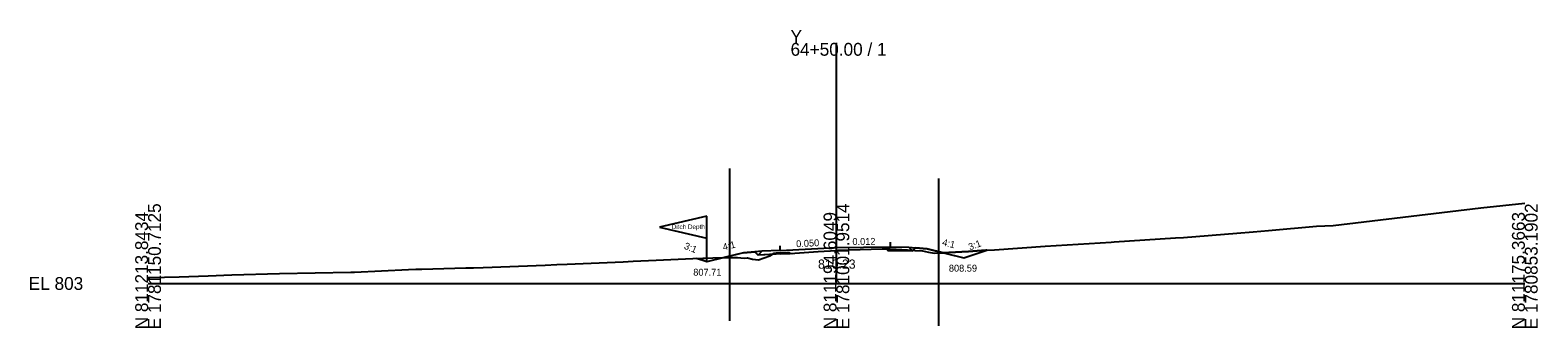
# Model space of a CAD drawing. Extents: x -12583 to 5303, y -44 to 25667.
# Drawn here: x 4974.3 to 5302.8, y 4990.3 to 5055.3 of the extents above; entities that cross this region are included whole.
import ezdxf

# ---------------------------------------------------------------- set-up
doc = ezdxf.new("R2010")
doc.units = 0
for name, color, linetype in [('Exist Cross Section Cell', 7, 'Continuous'), ('Exist XS Center Line Elevation Label', 7, 'Continuous'), ('Exist XS Ground Line', 7, 'Continuous'), ('Prop XS Ditch Slope Text', 7, 'Continuous'), ('Prop XS Ditch Standard Text', 7, 'Continuous'), ('Prop XS Dump Level', 7, 'Continuous'), ('Prop XS Earthwork Shape', 7, 'Continuous'), ('Prop XS EOT Tick Mark', 7, 'Continuous'), ('Prop XS Exc Vertical Line 1', 7, 'Continuous'), ('Prop XS Exc Vertical Line 2', 7, 'Continuous'), ('Prop XS Finish Grade', 7, 'Continuous'), ('Prop XS Finish Grade Earthwork', 7, 'Continuous'), ('Prop XS Finish Grade Paved Shoulder', 7, 'Continuous'), ('Prop XS Finish Grade Pavement', 7, 'Continuous'), ('Prop XS Pvmt Edge Slope', 7, 'Continuous'), ('Prop XS SE Text', 7, 'Continuous'), ('Prop XS Side Slope Text', 7, 'Continuous'), ('Prop XS Subgrade Earthwork', 7, 'Continuous'), ('Scratch_Level_3', 7, 'Continuous')]:
    doc.layers.add(name, color=color, linetype=linetype)

msp = doc.modelspace()

# ---------------------------------------------------------------- linework, layer by layer
at = {"layer": 'Exist Cross Section Cell'}
for p, q in [((5150, 5000), (5150, 5052.51)), ((5000, 5000), (5150, 5000)), ((5150, 5000), (5300, 5000))]:
    msp.add_line(p, q, dxfattribs=at)
at = {"layer": 'Exist XS Ground Line'}
for p, q in [((5290.45, 5016.51), (5300, 5017.5)), ((5258.26, 5012.65), (5290.45, 5016.51)), ((5225.66, 5010.04), (5237.25, 5010.99)), ((5237.25, 5010.99), (5240.79, 5011.24)), ((5240.79, 5011.24), (5244.18, 5011.56)), ((5244.18, 5011.56), (5254.6, 5012.48)), ((5254.6, 5012.48), (5258.26, 5012.65)), ((5139.9, 5006.57), (5146.05, 5007)), ((5146.05, 5007), (5150, 5007.23)), ((5150, 5007.23), (5150.4, 5007.25)), ((5150.4, 5007.25), (5159.95, 5007.53)), ((5159.95, 5007.53), (5161.22, 5007.57)), ((5161.22, 5007.57), (5161.69, 5007.54)), ((5161.69, 5007.54), (5163.01, 5007.47)), ((5163.01, 5007.47), (5167.07, 5007.23)), ((5167.07, 5007.23), (5168.78, 5007.13)), ((5168.78, 5007.13), (5170.03, 5006.85)), ((5170.03, 5006.85), (5171.35, 5006.6)), ((5174.5, 5006.79), (5178.76, 5007)), ((5178.76, 5007), (5182.57, 5007.24)), ((5182.57, 5007.24), (5184.42, 5007.37)), ((5184.42, 5007.37), (5195.45, 5008.16)), ((5195.45, 5008.16), (5209.85, 5009.04)), ((5209.85, 5009.04), (5210.54, 5009.08)), ((5210.54, 5009.08), (5223.85, 5009.94)), ((5223.85, 5009.94), (5225.66, 5010.04)), ((5073.04, 5003.47), (5086.52, 5003.98)), ((5086.52, 5003.98), (5089.09, 5004.12)), ((5089.09, 5004.12), (5091.35, 5004.19)), ((5091.35, 5004.19), (5103.54, 5004.75)), ((5103.54, 5004.75), (5105.68, 5004.88)), ((5105.68, 5004.88), (5110.71, 5005.11)), ((5110.71, 5005.11), (5118.74, 5005.46)), ((5118.74, 5005.46), (5123.1, 5005.57)), ((5123.1, 5005.57), (5125.46, 5005.65)), ((5125.46, 5005.65), (5128.46, 5005.64)), ((5128.46, 5005.64), (5129.92, 5005.52)), ((5129.92, 5005.52), (5130.59, 5005.62)), ((5130.59, 5005.62), (5131.69, 5005.32)), ((5131.69, 5005.32), (5133.04, 5005.15)), ((5133.04, 5005.15), (5135.5, 5006.06)), ((5135.5, 5006.06), (5136.4, 5006.64)), ((5136.4, 5006.64), (5136.89, 5006.7)), ((5136.89, 5006.7), (5139.24, 5006.8)), ((5139.24, 5006.8), (5139.62, 5006.79)), ((5139.62, 5006.79), (5139.9, 5006.57)), ((5171.35, 5006.6), (5173.43, 5006.7)), ((5173.43, 5006.7), (5174.5, 5006.79)), ((5000, 5001.28), (5000.41, 5001.29)), ((5000.41, 5001.29), (5006.8, 5001.45)), ((5006.8, 5001.45), (5013.13, 5001.69)), ((5013.13, 5001.69), (5018.28, 5001.86)), ((5018.28, 5001.86), (5028.66, 5002.21)), ((5028.66, 5002.21), (5044.19, 5002.44)), ((5044.19, 5002.44), (5044.95, 5002.47)), ((5044.95, 5002.47), (5056.77, 5003.02)), ((5056.77, 5003.02), (5058.32, 5003.1)), ((5058.32, 5003.1), (5059.63, 5003.15)), ((5059.63, 5003.15), (5069.24, 5003.41)), ((5069.24, 5003.41), (5070.88, 5003.41)), ((5070.88, 5003.41), (5073.04, 5003.47))]:
    msp.add_line(p, q, dxfattribs=at)
at = {"layer": 'Prop XS Dump Level'}
for p, q in [((5121.77, 5014.71), (5111.47, 5012.31)), ((5121.77, 5009.91), (5121.77, 5014.71)), ((5111.47, 5012.31), (5121.77, 5009.91)), ((5121.77, 5004.71), (5121.77, 5009.91)), ((5137.77, 5007.23), (5150, 5007.85)), ((5150, 5007.85), (5161.75, 5007.99))]:
    msp.add_line(p, q, dxfattribs=at)
at = {"layer": 'Prop XS Earthwork Shape'}
for points in [[(5128.46, 5005.64), (5129.92, 5005.52), (5130.59, 5005.62), (5131.69, 5005.32), (5133.04, 5005.15), (5135.5, 5006.06), (5135.95, 5006.35), (5132.93, 5006.2), (5132.22, 5006.91), (5129.77, 5006.71), (5125.52, 5005.65)], [(5163.01, 5007.47), (5166.71, 5007.26), (5166.56, 5007.1), (5161.75, 5007.2), (5161.22, 5007.19), (5161.22, 5007.57), (5161.69, 5007.54)], [(5171.35, 5006.6), (5173.34, 5006.7), (5169.75, 5007.59), (5167.25, 5007.79), (5166.71, 5007.26), (5167.07, 5007.23), (5168.78, 5007.13), (5170.03, 5006.85)], [(5173.34, 5006.7), (5177.75, 5005.59), (5182.74, 5007.25), (5182.57, 5007.24), (5178.76, 5007), (5174.5, 5006.79), (5173.43, 5006.7)], [(5125.46, 5005.65), (5125.52, 5005.65), (5121.77, 5004.71), (5119.49, 5005.47), (5123.1, 5005.57)], [(5136.89, 5006.7), (5139.24, 5006.8), (5139.62, 5006.79), (5139.9, 5006.57), (5139.9, 5006.55), (5137.81, 5006.44), (5135.95, 5006.35), (5136.4, 5006.64)]]:
    msp.add_lwpolyline(points, close=True, dxfattribs=at)
at = {"layer": 'Prop XS EOT Tick Mark'}
for p, q in [((5137.77, 5007.23), (5137.77, 5008.23)), ((5161.75, 5007.99), (5161.75, 5008.99))]:
    msp.add_line(p, q, dxfattribs=at)
at = {"layer": 'Prop XS Exc Vertical Line 1'}
msp.add_line((5126.78, 4991.83), (5126.78, 5025.07), dxfattribs=at)
at = {"layer": 'Prop XS Exc Vertical Line 2'}
msp.add_line((5172.33, 4990.78), (5172.33, 5022.88), dxfattribs=at)
at = {"layer": 'Prop XS Finish Grade'}
for p, q in [((5133.77, 5007.03), (5132.22, 5006.91)), ((5165.75, 5007.91), (5167.25, 5007.79))]:
    msp.add_line(p, q, dxfattribs=at)
at = {"layer": 'Prop XS Finish Grade Earthwork'}
for p, q in [((5129.77, 5006.71), (5132.22, 5006.91)), ((5167.25, 5007.79), (5169.75, 5007.59)), ((5169.75, 5007.59), (5177.75, 5005.59)), ((5177.75, 5005.59), (5182.74, 5007.25)), ((5121.77, 5004.71), (5119.49, 5005.47)), ((5129.77, 5006.71), (5121.77, 5004.71))]:
    msp.add_line(p, q, dxfattribs=at)
at = {"layer": 'Prop XS Finish Grade Paved Shoulder'}
for p, q in [((5137.77, 5007.23), (5133.77, 5007.03)), ((5161.75, 5007.99), (5165.75, 5007.91))]:
    msp.add_line(p, q, dxfattribs=at)
at = {"layer": 'Prop XS Finish Grade Pavement'}
for p, q in [((5137.77, 5007.23), (5150, 5007.85)), ((5150, 5007.85), (5161.75, 5007.99))]:
    msp.add_line(p, q, dxfattribs=at)
at = {"layer": 'Prop XS Pvmt Edge Slope'}
for p, q in [((5133.77, 5007.03), (5132.93, 5006.2)), ((5165.75, 5007.91), (5166.56, 5007.1))]:
    msp.add_line(p, q, dxfattribs=at)
at = {"layer": 'Prop XS Subgrade Earthwork'}
for p, q in [((5132.93, 5006.2), (5132.22, 5006.91)), ((5161.22, 5007.19), (5161.22, 5007.57)), ((5161.22, 5007.19), (5161.75, 5007.2)), ((5161.75, 5007.2), (5166.56, 5007.1)), ((5166.56, 5007.1), (5167.25, 5007.79)), ((5137.81, 5006.44), (5132.93, 5006.2)), ((5137.81, 5006.44), (5139.9, 5006.55)), ((5139.9, 5006.57), (5139.9, 5006.55))]:
    msp.add_line(p, q, dxfattribs=at)
at = {"layer": 'Scratch_Level_3'}
for points in [[(5161.69, 5007.54), (5163.01, 5007.47), (5166.71, 5007.26), (5166.56, 5007.1), (5161.75, 5007.2), (5161.22, 5007.19), (5161.22, 5007.57)], [(5139.24, 5006.8), (5139.62, 5006.79), (5139.9, 5006.57), (5139.9, 5006.55), (5137.81, 5006.44), (5135.95, 5006.35), (5136.4, 5006.64), (5136.89, 5006.7)]]:
    msp.add_lwpolyline(points, close=True, dxfattribs=at)

# ---------------------------------------------------------------- texts
at = {"layer": 'Exist Cross Section Cell'}
for s, p in [('Y', (5140, 5052.51)), ('64+50.00 / 1', (5140, 5049.71)), ('EL 803', (4974, 4998.6))]:
    msp.add_text(s, height=2.8, dxfattribs=at).set_placement(p)
for s, p in [('E 1781150.7125', (5002.8, 4990)), ('E 1781001.9514', (5152.8, 4990)), ('E 1780853.1902', (5302.8, 4990)), ('N 811213.8434', (5000, 4990)), ('N 811194.6049', (5150, 4990)), ('N 811175.3663', (5300, 4990))]:
    msp.add_text(s, height=2.8, rotation=90, dxfattribs=at).set_placement(p)
at = {"layer": 'Exist XS Center Line Elevation Label'}
msp.add_text('810.23', height=2, dxfattribs=at).set_placement((5145.99, 5003.23))
at = {"layer": 'Prop XS Ditch Slope Text'}
for rotation, p in [(14.0362, (5125.41, 5007.17)), (345.9638, (5172.94, 5008.34))]:
    msp.add_text('4:1', height=1.5, rotation=rotation, dxfattribs=at).set_placement(p)
at = {"layer": 'Prop XS Ditch Standard Text'}
for s, p in [('808.59', (5174.5, 5002.59)), ('807.71', (5118.8, 5001.71))]:
    msp.add_text(s, height=1.5, dxfattribs=at).set_placement(p)
at = {"layer": 'Prop XS Dump Level'}
for s, height, p in [('Ditch Depth', 1, (5114.11, 5011.88)), ('Eop', 0.3, (5161.22, 5007.27)), ('Case2', 0.04, (5169.75, 5007.55)), ('Case2', 0.04, (5129.77, 5006.67)), ('Eop', 0.3, (5139.9, 5006.27))]:
    msp.add_text(s, height=height, dxfattribs=at).set_placement(p)
at = {"layer": 'Prop XS SE Text'}
for s, rotation, p in [('0.050', 2.8624, (5141.26, 5007.91)), ('0.012', 0.7161, (5153.49, 5008.39))]:
    msp.add_text(s, height=1.5, rotation=rotation, dxfattribs=at).set_placement(p)
at = {"layer": 'Prop XS Side Slope Text'}
for rotation, p in [(338.2006, (5116.66, 5007.64)), (19.6191, (5179.07, 5007.22))]:
    msp.add_text('3:1', height=1.5, rotation=rotation, dxfattribs=at).set_placement(p)

doc.saveas('drawing.dxf')
